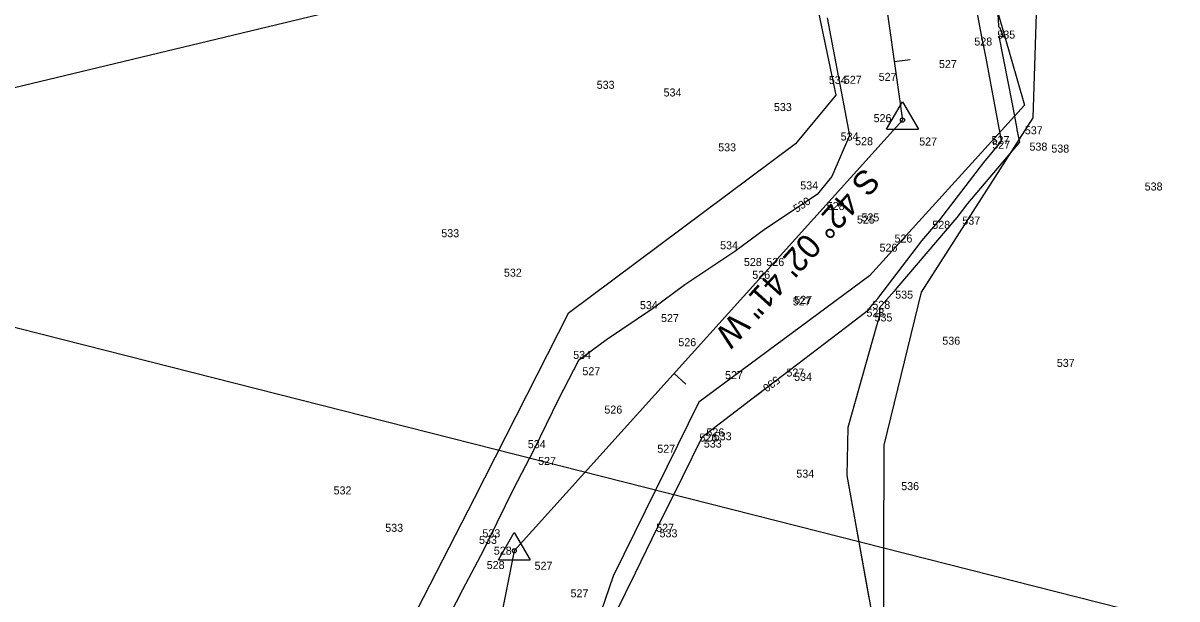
# Model space of a CAD drawing. Extents: x 1787461 to 1970323, y 938412 to 1118748.
# Drawn here: x 1967710 to 1967998.4, y 1118077.3 to 1118221.1 of the extents above; entities that cross this region are included whole.
import ezdxf

# ---------------------------------------------------------------- set-up
doc = ezdxf.new("R2010")
doc.units = 0
for name, color, linetype in [('Default', 7, 'Continuous'), ('HHA ADDITIONAL XSs', 7, 'Continuous'), ('Level 1', 7, 'Continuous'), ('RD_EX_DV_Prop', 7, 'Continuous'), ('RD_EX_Fence_Other', 7, 'Continuous'), ('RD_EX_H2O', 7, 'Continuous'), ('RD_HC_CL', 7, 'Continuous'), ('RD_HC_Data', 7, 'Continuous'), ('RD_HC_Data_Tic', 7, 'Continuous'), ('RD_SMD_Locator', 7, 'Continuous')]:
    doc.layers.add(name, color=color, linetype=linetype)

msp = doc.modelspace()

# ---------------------------------------------------------------- linework, layer by layer
at = {"layer": 'Default'}
for points in [[(1967952.3, 1118247.53), (1967953.8, 1118220.34), (1967953.84, 1118220.24), (1967953.91, 1118220.17), (1967954.01, 1118220.15), (1967954.09, 1118220.13), (1967955.11, 1118217.63), (1967954.18, 1118217.9), (1967953.93, 1118217.89), (1967957.24, 1118200.93), (1967958.39, 1118194.76), (1967958.45, 1118194.49), (1967959.04, 1118191.41), (1967946.09, 1118176.06), (1967943.43, 1118172.61), (1967928.39, 1118155.02), (1967927.76, 1118154.2), (1967924.04, 1118149.94), (1967924.16, 1118148.17), (1967923.34, 1118145.49), (1967916.17, 1118120.09), (1967915.91, 1118108.1), (1967926.19, 1118051.4)], [(1967952.3, 1118247.53), (1967953.8, 1118220.34), (1967953.84, 1118220.24), (1967953.91, 1118220.17), (1967954.01, 1118220.15), (1967954.09, 1118220.13), (1967955.11, 1118217.63), (1967954.18, 1118217.9), (1967953.93, 1118217.89), (1967957.24, 1118200.93), (1967958.39, 1118194.76), (1967958.45, 1118194.49), (1967959.04, 1118191.41), (1967946.09, 1118176.06), (1967943.43, 1118172.61), (1967928.39, 1118155.02), (1967927.76, 1118154.2), (1967924.04, 1118149.94), (1967924.16, 1118148.17), (1967923.34, 1118145.49), (1967916.17, 1118120.09), (1967915.91, 1118108.1), (1967921.45, 1118077.54)], [(1967952.3, 1118247.53), (1967953.8, 1118220.34), (1967953.84, 1118220.24), (1967953.91, 1118220.17), (1967954.01, 1118220.15), (1967954.09, 1118220.13), (1967955.11, 1118217.63), (1967954.18, 1118217.9), (1967953.93, 1118217.89), (1967957.24, 1118200.93), (1967958.39, 1118194.76), (1967958.45, 1118194.49), (1967959.04, 1118191.41), (1967946.09, 1118176.06), (1967943.43, 1118172.61), (1967928.39, 1118155.02), (1967927.76, 1118154.2), (1967924.04, 1118149.94), (1967924.16, 1118148.17), (1967923.34, 1118145.49), (1967916.17, 1118120.09), (1967915.91, 1118108.1), (1967921.45, 1118077.54)], [(1967952.3, 1118247.53), (1967953.8, 1118220.34), (1967953.84, 1118220.24), (1967953.91, 1118220.17), (1967954.01, 1118220.15), (1967954.09, 1118220.13), (1967955.11, 1118217.63), (1967954.18, 1118217.9), (1967953.93, 1118217.89), (1967957.24, 1118200.93), (1967958.39, 1118194.76), (1967958.45, 1118194.49), (1967959.04, 1118191.41), (1967946.09, 1118176.06), (1967943.43, 1118172.61), (1967928.39, 1118155.02), (1967927.76, 1118154.2), (1967924.04, 1118149.94), (1967924.16, 1118148.17), (1967923.34, 1118145.49), (1967916.17, 1118120.09), (1967915.91, 1118108.1), (1967921.45, 1118077.54)], [(1967952.3, 1118247.53), (1967953.8, 1118220.34), (1967953.84, 1118220.24), (1967953.91, 1118220.17), (1967954.01, 1118220.15), (1967954.09, 1118220.13), (1967955.11, 1118217.63), (1967954.18, 1118217.9), (1967953.93, 1118217.89), (1967957.24, 1118200.93), (1967958.39, 1118194.76), (1967958.45, 1118194.49), (1967959.04, 1118191.41), (1967946.09, 1118176.06), (1967943.43, 1118172.61), (1967928.39, 1118155.02), (1967927.76, 1118154.2), (1967924.04, 1118149.94), (1967924.16, 1118148.17), (1967923.34, 1118145.49), (1967916.17, 1118120.09), (1967915.91, 1118108.1), (1967921.45, 1118077.54)], [(1967952.3, 1118247.53), (1967953.8, 1118220.34), (1967953.84, 1118220.24), (1967953.91, 1118220.17), (1967954.01, 1118220.15), (1967954.09, 1118220.13), (1967955.11, 1118217.63), (1967954.18, 1118217.9), (1967953.93, 1118217.89), (1967957.24, 1118200.93), (1967958.39, 1118194.76), (1967958.45, 1118194.49), (1967959.04, 1118191.41), (1967946.09, 1118176.06), (1967943.43, 1118172.61), (1967928.39, 1118155.02), (1967927.76, 1118154.2), (1967924.04, 1118149.94), (1967924.16, 1118148.17), (1967923.34, 1118145.49), (1967916.17, 1118120.09), (1967915.91, 1118108.1), (1967921.45, 1118077.54)], [(1967952.3, 1118247.53), (1967953.8, 1118220.34), (1967953.84, 1118220.24), (1967953.91, 1118220.17), (1967954.01, 1118220.15), (1967954.09, 1118220.13), (1967955.11, 1118217.63), (1967954.18, 1118217.9), (1967953.93, 1118217.89), (1967957.24, 1118200.93), (1967958.39, 1118194.76), (1967958.45, 1118194.49), (1967959.04, 1118191.41), (1967946.09, 1118176.06), (1967943.43, 1118172.61), (1967928.39, 1118155.02), (1967927.76, 1118154.2), (1967924.04, 1118149.94), (1967924.16, 1118148.17), (1967923.34, 1118145.49), (1967916.17, 1118120.09), (1967915.91, 1118108.1), (1967921.45, 1118077.54)], [(1967858.16, 1118073.86), (1967863.11, 1118083.83), (1967868.71, 1118095.35), (1967874.84, 1118107.68), (1967879.73, 1118117.72), (1967880.44, 1118118.26), (1967881.88, 1118119.35), (1967891.88, 1118127.03), (1967901.62, 1118134.41), (1967915.56, 1118145.13), (1967921.32, 1118149.52), (1967922.43, 1118150.97), (1967923.64, 1118152.36), (1967934.63, 1118166.75), (1967939.13, 1118172.01), (1967950.15, 1118186.33), (1967954.62, 1118191.63), (1967954.41, 1118192.69), (1967954.26, 1118193.55), (1967950.73, 1118212.38), (1967949.61, 1118218.08), (1967946.31, 1118235.75)], [(1967899.2, 1118132.58), (1967901.62, 1118134.41), (1967915.56, 1118145.13), (1967921.32, 1118149.52), (1967922.43, 1118150.97), (1967923.64, 1118152.36), (1967934.63, 1118166.75), (1967939.13, 1118172.01), (1967950.15, 1118186.33), (1967954.62, 1118191.63), (1967954.41, 1118192.69), (1967954.26, 1118193.55), (1967950.73, 1118212.38), (1967949.61, 1118218.08), (1967946.31, 1118235.75)], [(1967899.2, 1118132.58), (1967901.62, 1118134.41), (1967915.56, 1118145.13), (1967921.32, 1118149.52), (1967922.43, 1118150.97), (1967923.64, 1118152.36), (1967934.63, 1118166.75), (1967939.13, 1118172.01), (1967950.15, 1118186.33), (1967954.62, 1118191.63), (1967954.41, 1118192.69), (1967954.26, 1118193.55), (1967950.73, 1118212.38), (1967949.61, 1118218.08), (1967946.31, 1118235.75)], [(1967899.2, 1118132.58), (1967901.62, 1118134.41), (1967915.56, 1118145.13), (1967921.32, 1118149.52), (1967922.43, 1118150.97), (1967923.64, 1118152.36), (1967934.63, 1118166.75), (1967939.13, 1118172.01), (1967950.15, 1118186.33), (1967954.62, 1118191.63), (1967954.41, 1118192.69), (1967954.26, 1118193.55), (1967950.73, 1118212.38), (1967949.61, 1118218.08), (1967946.31, 1118235.75)], [(1967899.2, 1118132.58), (1967901.62, 1118134.41), (1967915.56, 1118145.13), (1967921.32, 1118149.52), (1967922.43, 1118150.97), (1967923.64, 1118152.36), (1967934.63, 1118166.75), (1967939.13, 1118172.01), (1967950.15, 1118186.33), (1967954.62, 1118191.63), (1967954.41, 1118192.69), (1967954.26, 1118193.55), (1967950.73, 1118212.38), (1967949.61, 1118218.08), (1967946.31, 1118235.75)], [(1967899.2, 1118132.58), (1967901.62, 1118134.41), (1967915.56, 1118145.13), (1967921.32, 1118149.52), (1967922.43, 1118150.97), (1967923.64, 1118152.36), (1967934.63, 1118166.75), (1967939.13, 1118172.01), (1967950.15, 1118186.33), (1967954.62, 1118191.63), (1967954.41, 1118192.69), (1967954.26, 1118193.55), (1967950.73, 1118212.38), (1967949.61, 1118218.08), (1967946.31, 1118235.75)], [(1967899.2, 1118132.58), (1967901.62, 1118134.41), (1967915.56, 1118145.13), (1967921.32, 1118149.52), (1967922.43, 1118150.97), (1967923.64, 1118152.36), (1967934.63, 1118166.75), (1967939.13, 1118172.01), (1967950.15, 1118186.33), (1967954.62, 1118191.63), (1967954.41, 1118192.69), (1967954.26, 1118193.55), (1967950.73, 1118212.38), (1967949.61, 1118218.08), (1967946.31, 1118235.75)], [(1967910.98, 1118222.44), (1967913.74, 1118207.95), (1967914.85, 1118202.27), (1967916.6, 1118193.09), (1967912.18, 1118182.84), (1967908.51, 1118178.31), (1967895.58, 1118169.76), (1967887.93, 1118164.05), (1967875.39, 1118155.74), (1967867.37, 1118149.75), (1967855.82, 1118142.06), (1967848.87, 1118136.87), (1967843.85, 1118127.2), (1967837.66, 1118114.55), (1967832.51, 1118104.67), (1967826.45, 1118092.23), (1967826.08, 1118091.53), (1967825.08, 1118089.48), (1967819.89, 1118079.58), (1967813.61, 1118067.44)], [(1967910.98, 1118222.44), (1967913.74, 1118207.95), (1967914.85, 1118202.27), (1967916.6, 1118193.09), (1967912.18, 1118182.84), (1967908.51, 1118178.31), (1967907.47, 1118177.62)], [(1967910.98, 1118222.44), (1967913.74, 1118207.95), (1967914.85, 1118202.27), (1967916.6, 1118193.09), (1967912.18, 1118182.84), (1967908.51, 1118178.31), (1967907.47, 1118177.62)], [(1967910.98, 1118222.44), (1967913.74, 1118207.95), (1967914.85, 1118202.27), (1967916.6, 1118193.09), (1967912.18, 1118182.84), (1967908.51, 1118178.31), (1967907.47, 1118177.62)], [(1967910.98, 1118222.44), (1967913.74, 1118207.95), (1967914.85, 1118202.27), (1967916.6, 1118193.09), (1967912.18, 1118182.84), (1967908.51, 1118178.31), (1967907.47, 1118177.62)], [(1967910.98, 1118222.44), (1967913.74, 1118207.95), (1967914.85, 1118202.27), (1967916.6, 1118193.09), (1967912.18, 1118182.84), (1967908.51, 1118178.31), (1967907.47, 1118177.62)], [(1967910.98, 1118222.44), (1967913.74, 1118207.95), (1967914.85, 1118202.27), (1967916.6, 1118193.09), (1967912.18, 1118182.84), (1967908.51, 1118178.31), (1967907.47, 1118177.62)], [(1967902.47, 1118174.31), (1967895.58, 1118169.76), (1967887.93, 1118164.05), (1967875.39, 1118155.74), (1967867.37, 1118149.75), (1967855.82, 1118142.06), (1967848.87, 1118136.87), (1967843.85, 1118127.2), (1967837.66, 1118114.55), (1967832.51, 1118104.67), (1967826.45, 1118092.23), (1967826.08, 1118091.53), (1967825.08, 1118089.48), (1967819.89, 1118079.58), (1967813.61, 1118067.44), (1967808.01, 1118056.77), (1967802.13, 1118045.42), (1967801.64, 1118044.48), (1967801.57, 1118044.34), (1967799.9, 1118032.65), (1967797.82, 1118019.49), (1967797.03, 1118014.01)], [(1967902.47, 1118174.31), (1967895.58, 1118169.76), (1967887.93, 1118164.05), (1967875.39, 1118155.74), (1967867.37, 1118149.75), (1967855.82, 1118142.06), (1967848.87, 1118136.87), (1967843.85, 1118127.2), (1967837.66, 1118114.55), (1967832.51, 1118104.67), (1967826.45, 1118092.23), (1967826.08, 1118091.53), (1967825.08, 1118089.48), (1967819.89, 1118079.58), (1967813.61, 1118067.44), (1967808.01, 1118056.77), (1967802.13, 1118045.42), (1967801.64, 1118044.48), (1967801.57, 1118044.34), (1967799.9, 1118032.65), (1967797.82, 1118019.49), (1967797.03, 1118014.01)], [(1967902.47, 1118174.31), (1967895.58, 1118169.76), (1967887.93, 1118164.05), (1967875.39, 1118155.74), (1967867.37, 1118149.75), (1967855.82, 1118142.06), (1967848.87, 1118136.87), (1967843.85, 1118127.2), (1967837.66, 1118114.55), (1967832.51, 1118104.67), (1967826.45, 1118092.23), (1967826.08, 1118091.53), (1967825.08, 1118089.48), (1967819.89, 1118079.58), (1967813.61, 1118067.44), (1967808.01, 1118056.77), (1967802.13, 1118045.42), (1967801.64, 1118044.48), (1967801.57, 1118044.34), (1967799.9, 1118032.65), (1967797.82, 1118019.49), (1967797.03, 1118014.01)], [(1967902.47, 1118174.31), (1967895.58, 1118169.76), (1967887.93, 1118164.05), (1967875.39, 1118155.74), (1967867.37, 1118149.75), (1967855.82, 1118142.06), (1967848.87, 1118136.87), (1967843.85, 1118127.2), (1967837.66, 1118114.55), (1967832.51, 1118104.67), (1967826.45, 1118092.23), (1967826.08, 1118091.53), (1967825.08, 1118089.48), (1967819.89, 1118079.58), (1967813.61, 1118067.44), (1967808.01, 1118056.77), (1967802.13, 1118045.42), (1967801.64, 1118044.48), (1967801.57, 1118044.34), (1967799.9, 1118032.65), (1967797.82, 1118019.49), (1967797.03, 1118014.01)], [(1967902.47, 1118174.31), (1967895.58, 1118169.76), (1967887.93, 1118164.05), (1967875.39, 1118155.74), (1967867.37, 1118149.75), (1967855.82, 1118142.06), (1967848.87, 1118136.87), (1967843.85, 1118127.2), (1967837.66, 1118114.55), (1967832.51, 1118104.67), (1967826.45, 1118092.23), (1967826.08, 1118091.53), (1967825.08, 1118089.48), (1967819.89, 1118079.58), (1967813.61, 1118067.44), (1967808.01, 1118056.77), (1967802.13, 1118045.42), (1967801.64, 1118044.48), (1967801.57, 1118044.34), (1967799.9, 1118032.65), (1967797.82, 1118019.49), (1967797.03, 1118014.01)], [(1967902.47, 1118174.31), (1967895.58, 1118169.76), (1967887.93, 1118164.05), (1967875.39, 1118155.74), (1967867.37, 1118149.75), (1967855.82, 1118142.06), (1967848.87, 1118136.87), (1967843.85, 1118127.2), (1967837.66, 1118114.55), (1967832.51, 1118104.67), (1967826.45, 1118092.23), (1967826.08, 1118091.53), (1967825.08, 1118089.48), (1967819.89, 1118079.58), (1967813.61, 1118067.44), (1967808.01, 1118056.77), (1967802.13, 1118045.42), (1967801.64, 1118044.48), (1967801.57, 1118044.34), (1967799.9, 1118032.65), (1967797.82, 1118019.49), (1967797.03, 1118014.01)], [(1967828.54, 1117946.2), (1967828.33, 1117959.79), (1967828.34, 1117970.11), (1967828.12, 1117984.79), (1967832.39, 1117998.26), (1967835.19, 1118007.59), (1967837.84, 1118016.4), (1967842.61, 1118031.47), (1967845.22, 1118038.9), (1967849.58, 1118050.38), (1967853.13, 1118060.57), (1967858.16, 1118073.86), (1967863.11, 1118083.83), (1967868.71, 1118095.35), (1967874.84, 1118107.68), (1967879.73, 1118117.72), (1967880.44, 1118118.26), (1967881.88, 1118119.35), (1967891.88, 1118127.03), (1967894.42, 1118128.95)], [(1967828.54, 1117946.2), (1967828.33, 1117959.79), (1967828.34, 1117970.11), (1967828.12, 1117984.79), (1967832.39, 1117998.26), (1967835.19, 1118007.59), (1967837.84, 1118016.4), (1967842.61, 1118031.47), (1967845.22, 1118038.9), (1967849.58, 1118050.38), (1967853.13, 1118060.57), (1967858.16, 1118073.86), (1967863.11, 1118083.83), (1967868.71, 1118095.35), (1967874.84, 1118107.68), (1967879.73, 1118117.72), (1967880.44, 1118118.26), (1967881.88, 1118119.35), (1967891.88, 1118127.03), (1967894.42, 1118128.95)], [(1967828.54, 1117946.2), (1967828.33, 1117959.79), (1967828.34, 1117970.11), (1967828.12, 1117984.79), (1967832.39, 1117998.26), (1967835.19, 1118007.59), (1967837.84, 1118016.4), (1967842.61, 1118031.47), (1967845.22, 1118038.9), (1967849.58, 1118050.38), (1967853.13, 1118060.57), (1967858.16, 1118073.86), (1967863.11, 1118083.83), (1967868.71, 1118095.35), (1967874.84, 1118107.68), (1967879.73, 1118117.72), (1967880.44, 1118118.26), (1967881.88, 1118119.35), (1967891.88, 1118127.03), (1967894.42, 1118128.95)], [(1967828.54, 1117946.2), (1967828.33, 1117959.79), (1967828.34, 1117970.11), (1967828.12, 1117984.79), (1967832.39, 1117998.26), (1967835.19, 1118007.59), (1967837.84, 1118016.4), (1967842.61, 1118031.47), (1967845.22, 1118038.9), (1967849.58, 1118050.38), (1967853.13, 1118060.57), (1967858.16, 1118073.86), (1967863.11, 1118083.83), (1967868.71, 1118095.35), (1967874.84, 1118107.68), (1967879.73, 1118117.72), (1967880.44, 1118118.26), (1967881.88, 1118119.35), (1967891.88, 1118127.03), (1967894.42, 1118128.95)], [(1967828.54, 1117946.2), (1967828.33, 1117959.79), (1967828.34, 1117970.11), (1967828.12, 1117984.79), (1967832.39, 1117998.26), (1967835.19, 1118007.59), (1967837.84, 1118016.4), (1967842.61, 1118031.47), (1967845.22, 1118038.9), (1967849.58, 1118050.38), (1967853.13, 1118060.57), (1967858.16, 1118073.86), (1967863.11, 1118083.83), (1967868.71, 1118095.35), (1967874.84, 1118107.68), (1967879.73, 1118117.72), (1967880.44, 1118118.26), (1967881.88, 1118119.35), (1967891.88, 1118127.03), (1967894.42, 1118128.95)], [(1967828.54, 1117946.2), (1967828.33, 1117959.79), (1967828.34, 1117970.11), (1967828.12, 1117984.79), (1967832.39, 1117998.26), (1967835.19, 1118007.59), (1967837.84, 1118016.4), (1967842.61, 1118031.47), (1967845.22, 1118038.9), (1967849.58, 1118050.38), (1967853.13, 1118060.57), (1967858.16, 1118073.86), (1967863.11, 1118083.83), (1967868.71, 1118095.35), (1967874.84, 1118107.68), (1967879.73, 1118117.72), (1967880.44, 1118118.26), (1967881.88, 1118119.35), (1967891.88, 1118127.03), (1967894.42, 1118128.95)]]:
    msp.add_lwpolyline(points, dxfattribs=at)
at = {"layer": 'HHA ADDITIONAL XSs'}
msp.add_lwpolyline([(1969084.5, 1118456.85), (1968180.14, 1118318.35), (1967682.43, 1118198.9), (1966417.22, 1117847.18)], dxfattribs=at)
at = {"layer": 'Level 1'}
msp.add_line((1968061.02, 1118055.58), (1967665.18, 1118155.96), dxfattribs=at)
at = {"layer": 'RD_EX_DV_Prop'}
for p, q in [((1967910.14, 1118337.02), (1967929.83, 1118196.9)), ((1967929.83, 1118196.9), (1967832.81, 1118089.32)), ((1967832.81, 1118089.32), (1967803.58, 1117944.23))]:
    msp.add_line(p, q, dxfattribs=at)
at = {"layer": 'RD_EX_Fence_Other'}
msp.add_lwpolyline([(1967919.7, 1118378.02), (1967936.64, 1118351.76), (1967953.58, 1118310.67), (1967964.44, 1118259.92), (1967962.38, 1118197.45), (1967934.48, 1118153.92), (1967925.2, 1118115.74), (1967925.02, 1118060.61), (1967940.38, 1118016.99), (1967944.7, 1118004.73)], dxfattribs=at)
at = {"layer": 'RD_EX_H2O'}
for points in [[(1967851.18, 1118399.4), (1967910.98, 1118393), (1967923.85, 1118346.18), (1967942.91, 1118303.76), (1967945.44, 1118252.51), (1967960.35, 1118200.64), (1967921.61, 1118157.98), (1967878.95, 1118126.47), (1967857.49, 1118083), (1967842.73, 1118040.05), (1967828.54, 1117994.01), (1967828.4, 1117944.09), (1967833.42, 1117912.71)], [(1967847.31, 1118356.81), (1967879.15, 1118347.14), (1967885.7, 1118340.94), (1967895.17, 1118292.21), (1967905.1, 1118241.75), (1967913.15, 1118203.17), (1967903.06, 1118190.95), (1967846.3, 1118148.6), (1967822.76, 1118102.41), (1967798.93, 1118056.05), (1967790.6, 1118001.77), (1967788.7, 1117944.97), (1967797.09, 1117898.55), (1967795.44, 1117890.32)]]:
    msp.add_lwpolyline(points, dxfattribs=at)
at = {"layer": 'RD_HC_CL'}
for p, q in [((1967910.14, 1118337.02), (1967929.83, 1118196.9)), ((1967929.83, 1118196.9), (1967832.81, 1118089.32)), ((1967832.81, 1118089.32), (1967803.58, 1117944.23))]:
    msp.add_line(p, q, dxfattribs=at)
at = {"layer": 'RD_HC_Data'}
for p, q in [((1967925.85, 1118194.61), (1967929.83, 1118201.49)), ((1967929.83, 1118201.49), (1967933.8, 1118194.61)), ((1967925.85, 1118194.61), (1967933.8, 1118194.61)), ((1967828.84, 1118087.03), (1967832.81, 1118093.91)), ((1967832.81, 1118093.91), (1967836.78, 1118087.03)), ((1967828.84, 1118087.03), (1967836.78, 1118087.03))]:
    msp.add_line(p, q, dxfattribs=at)
for centre in [(1967929.83, 1118196.9), (1967832.81, 1118089.32)]:
    msp.add_circle(centre, 0.529, dxfattribs=at)
at = {"layer": 'RD_HC_Data_Tic'}
for p, q in [((1967927.77, 1118211.52), (1967931.73, 1118212.07)), ((1967872.74, 1118133.6), (1967875.71, 1118130.92))]:
    msp.add_line(p, q, dxfattribs=at)
at = {"layer": 'RD_SMD_Locator'}
for centre in [(1967929.83, 1118196.9), (1967832.81, 1118089.32)]:
    msp.add_circle(centre, 0.001, dxfattribs=at)

# ---------------------------------------------------------------- texts
at = {"layer": 'Default'}
for s, p in [('535', (1967953.54, 1118217.26)), ('528', (1967947.79, 1118215.53)), ('527', (1967938.95, 1118209.91)), ('533', (1967853.4, 1118204.72)), ('534', (1967911.43, 1118205.92)), ('527', (1967915.17, 1118205.97)), ('527', (1967923.89, 1118206.71)), ('534', (1967870.12, 1118202.81)), ('533', (1967897.7, 1118199.16)), ('526', (1967922.62, 1118196.39)), ('537', (1967960.41, 1118193.36)), ('534', (1967914.38, 1118191.81)), ('528', (1967917.99, 1118190.64)), ('527', (1967934.01, 1118190.56)), ('527', (1967952.09, 1118190.91)), ('533', (1967883.77, 1118189.11)), ('527', (1967952.29, 1118189.75)), ('538', (1967961.58, 1118189.28)), ('538', (1967967.04, 1118188.79)), ('534', (1967904.29, 1118179.59)), ('538', (1967990.37, 1118179.32)), ('528', (1967910.91, 1118174.45)), ('525', (1967918.45, 1118171.07)), ('525', (1967919.58, 1118171.6)), ('528', (1967937.29, 1118169.75)), ('537', (1967944.8, 1118170.8)), ('533', (1967814.56, 1118167.65)), ('534', (1967884.25, 1118164.64)), ('526', (1967924.1, 1118164.05)), ('526', (1967927.84, 1118166.33)), ('528', (1967890.19, 1118160.46)), ('526', (1967895.81, 1118160.48)), ('532', (1967830.21, 1118157.79)), ('526', (1967892.29, 1118157.27)), ('534', (1967864.21, 1118149.69)), ('527', (1967902.41, 1118150.61)), ('527', (1967902.78, 1118151.01)), ('528', (1967922.3, 1118149.76)), ('535', (1967928.01, 1118152.31)), ('528', (1967920.83, 1118147.81)), ('527', (1967869.48, 1118146.46)), ('535', (1967922.84, 1118146.62)), ('526', (1967873.81, 1118140.43)), ('536', (1967939.79, 1118140.81)), ('534', (1967847.52, 1118137.25)), ('537', (1967968.41, 1118135.26)), ('527', (1967849.83, 1118133.18)), ('527', (1967900.82, 1118132.86)), ('527', (1967885.48, 1118132.21)), ('534', (1967902.75, 1118131.78)), ('526', (1967855.32, 1118123.6)), ('526', (1967880.81, 1118117.91)), ('534', (1967836.18, 1118114.97)), ('526', (1967879.07, 1118116.61)), ('533', (1967880.18, 1118115.11)), ('533', (1967882.66, 1118116.94)), ('527', (1967868.55, 1118113.81)), ('527', (1967838.76, 1118110.77)), ('534', (1967903.3, 1118107.6)), ('532', (1967787.64, 1118103.41)), ('536', (1967929.51, 1118104.48)), ('533', (1967800.55, 1118094.07)), ('533', (1967824.83, 1118092.7)), ('527', (1967868.26, 1118094.07)), ('533', (1967869.11, 1118092.7)), ('533', (1967823.99, 1118091.05)), ('528', (1967827.68, 1118088.36)), ('528', (1967825.91, 1118084.77)), ('527', (1967837.87, 1118084.59)), ('527', (1967846.86, 1118077.71))]:
    msp.add_text(s, height=2, dxfattribs=at).set_placement(p)
for rotation, p in [(33.4381, (1967903.37, 1118173.71)), (33.4381, (1967903.37, 1118173.71)), (33.4381, (1967903.37, 1118173.71)), (33.4381, (1967903.37, 1118173.71)), (33.4381, (1967903.37, 1118173.71)), (33.4381, (1967903.37, 1118173.71)), (217.2025, (1967898.26, 1118133.12)), (217.2025, (1967898.26, 1118133.12)), (217.2025, (1967898.26, 1118133.12)), (217.2025, (1967898.26, 1118133.12)), (217.2025, (1967898.26, 1118133.12)), (217.2025, (1967898.26, 1118133.12))]:
    msp.add_text('530', height=2, rotation=rotation, dxfattribs=at).set_placement(p)
at = {"layer": 'RD_HC_Data'}
msp.add_text('S 42%%d 02\' 41" W', height=6, rotation=227.9551, dxfattribs=at).set_placement((1967920.25, 1118185.33))

doc.saveas('drawing.dxf')
